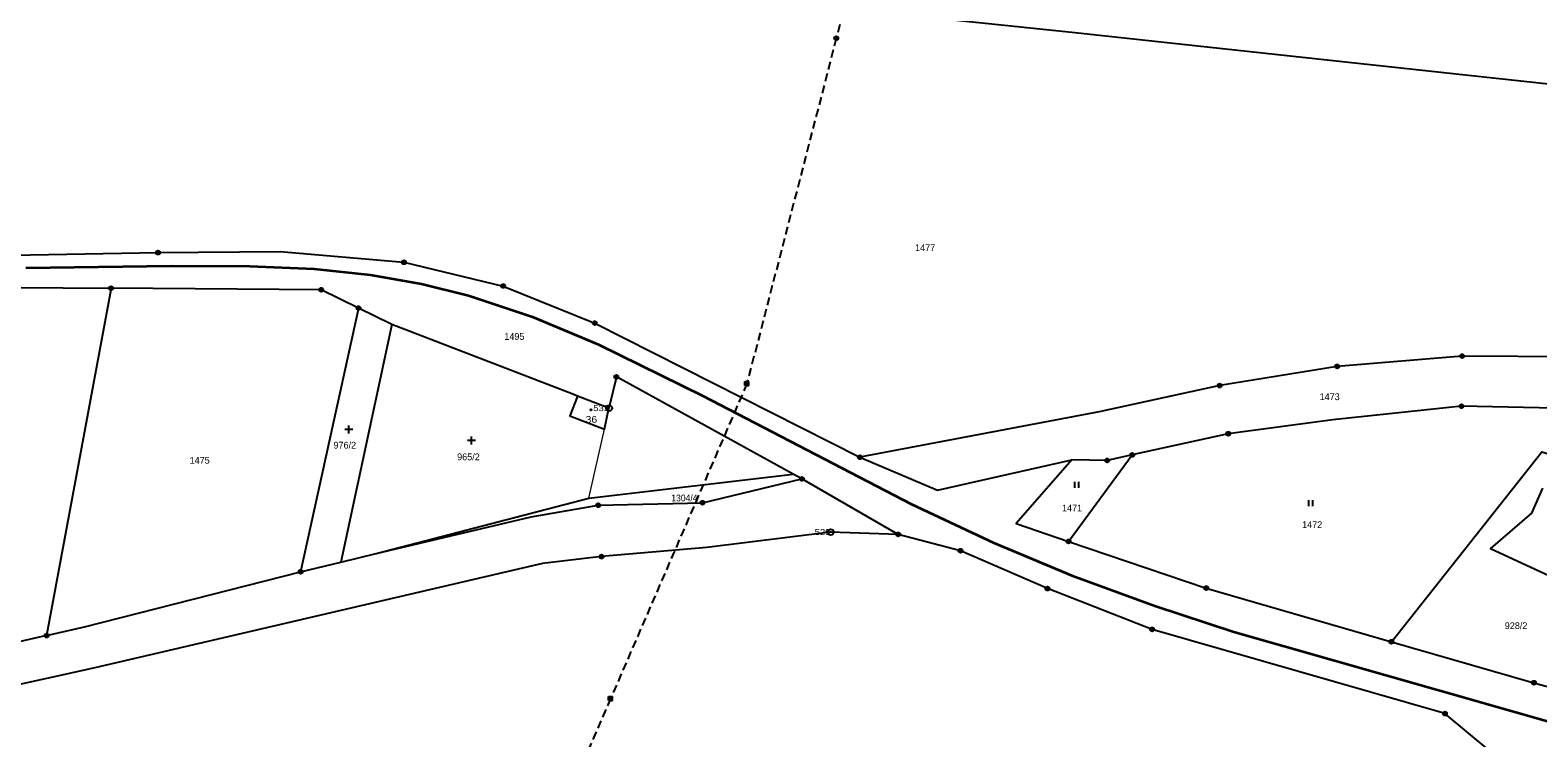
# Model space of a CAD drawing. Extents: x -872229 to -869198, y -1075981 to -1074329.
# Drawn here: x -871585.9 to -871207, y -1075387.5 to -1075209.5 of the extents above; entities that cross this region are included whole.
import ezdxf
from ezdxf.enums import TextEntityAlignment as Align

# ---------------------------------------------------------------- set-up
doc = ezdxf.new("R2010")
doc.units = 0
doc.header["$LTSCALE"] = 0.68
doc.linetypes.add('MEDIUM_DASHED', pattern=[4.5, 3, -1.5])
for name, color, linetype, lineweight in [('1', 7, 'Continuous', 25), ('3', 7, 'Continuous', 25), ('4', 7, 'Continuous', 13), ('5', 7, 'Continuous', 25), ('6', 7, 'Continuous', 25), ('8', 7, 'Continuous', 25)]:
    doc.layers.add(name, color=color, linetype=linetype, lineweight=lineweight)
doc.layers.add('2', color=7, linetype='Continuous')

msp = doc.modelspace()

# ---------------------------------------------------------------- linework, layer by layer
at = {"layer": '1'}
for p, q in [((-871391.97, -1075322.38), (-871394.16, -1075321.17)), ((-871367.76, -1075336.32), (-871391.97, -1075322.38)), ((-871517.94, -1075345.74), (-871507.87, -1075343.3))]:
    msp.add_line(p, q, dxfattribs=at)
for points in [[(-871152.53, -1075228.75), (-871324.15, -1075210.15), (-871498.95, -1075191.88), (-871564.6, -1075180.17), (-871590.36, -1075167.06), (-871608.79, -1075266.42)], [(-871673.37, -1075268.15), (-871670.8, -1075268.84), (-871646.86, -1075272.41), (-871613.89, -1075274.07), (-871565.58, -1075274.43)], [(-871608.79, -1075266.42), (-871553.79, -1075265.47), (-871523.09, -1075265.22), (-871491.97, -1075267.91), (-871467.05, -1075273.87), (-871444.01, -1075283.21), (-871377.38, -1075316.93)], [(-871503.38, -1075279.44), (-871512.76, -1075274.83), (-871565.58, -1075274.43), (-871581.77, -1075361.77)], [(-871495.01, -1075283.55), (-871503.38, -1075279.44), (-871517.94, -1075345.74)], [(-871495.01, -1075283.55), (-871507.87, -1075343.3), (-871498.97, -1075341.15)], [(-871448.37, -1075301.54), (-871449.54, -1075301.09), (-871495.01, -1075283.55)], [(-871197.94, -1075291.72), (-871226.01, -1075291.51), (-871257.41, -1075294.08), (-871286.96, -1075298.91), (-871317.28, -1075305.51), (-871377.38, -1075316.93)], [(-871394.16, -1075321.17), (-871438.58, -1075296.72), (-871440.45, -1075304.59)], [(-871198.89, -1075304.69), (-871226.19, -1075304.09), (-871258.51, -1075307.55), (-871284.79, -1075311.01), (-871308.94, -1075316.35)], [(-871243.8, -1075363.33), (-871206.01, -1075315.54), (-871202.96, -1075316.49), (-871198.89, -1075304.69)], [(-871377.38, -1075316.93), (-871357.91, -1075325.19), (-871324.12, -1075317.6)], [(-871324.12, -1075317.6), (-871338.12, -1075333.63), (-871324.93, -1075338.1), (-871308.94, -1075316.35)], [(-871308.94, -1075316.35), (-871315.25, -1075317.74), (-871324.12, -1075317.6)], [(-871498.97, -1075341.15), (-871445.51, -1075327.21), (-871394.16, -1075321.17)], [(-871498.97, -1075341.15), (-871459.98, -1075331.95), (-871443.14, -1075329), (-871416.95, -1075328.37), (-871391.97, -1075322.38)], [(-871205.8, -1075324.68), (-871208.57, -1075330.98), (-871218.91, -1075339.87), (-871180.67, -1075357.59)], [(-871367.76, -1075336.32), (-871384.74, -1075335.75), (-871415.81, -1075339.64), (-871442.3, -1075341.92), (-871457.12, -1075343.68), (-871569.63, -1075369.86), (-871593.96, -1075375.27), (-871613.49, -1075377.17), (-871630.54, -1075375.46), (-871654.44, -1075369.56), (-871683.36, -1075359.66)], [(-871212.24, -1075392.84), (-871218.94, -1075390.82), (-871230.33, -1075381.38), (-871303.93, -1075360.22), (-871330.24, -1075349.97), (-871352.11, -1075340.43), (-871367.76, -1075336.32)], [(-871581.77, -1075361.77), (-871595.26, -1075364.86), (-871610.89, -1075365.32), (-871627.46, -1075364.95), (-871651.19, -1075358.47), (-871705.48, -1075340.14)], [(-871324.93, -1075338.1), (-871290.33, -1075349.84), (-871243.8, -1075363.33)], [(-871581.77, -1075361.77), (-871572.27, -1075359.6), (-871517.94, -1075345.74)], [(-871243.8, -1075363.33), (-871207.98, -1075373.63), (-871201.2, -1075375.48), (-871200.62, -1075375.46)]]:
    msp.add_lwpolyline(points, dxfattribs=at)
msp.add_lwpolyline([(-871448.37, -1075301.54), (-871450.3, -1075306.53), (-871441.59, -1075309.84), (-871440.45, -1075304.59)], close=True, dxfattribs=at)
at = {"layer": '3'}
for p, q in [((-871504.829, -1075309.941), (-871506.831, -1075309.941)), ((-871505.83, -1075310.94), (-871505.83, -1075308.94)), ((-871473.959, -1075312.711), (-871475.961, -1075312.711)), ((-871474.96, -1075313.71), (-871474.96, -1075311.71)), ((-871323.381, -1075324.65), (-871323.381, -1075323.15)), ((-871322.38, -1075324.65), (-871322.38, -1075323.15)), ((-871264.561, -1075329.2), (-871264.561, -1075327.7)), ((-871263.56, -1075329.2), (-871263.56, -1075327.7))]:
    msp.add_line(p, q, dxfattribs=at)
at = {"layer": '4'}
msp.add_line((-871445.51, -1075327.21), (-871441.59, -1075309.84), dxfattribs=at)
at = {"layer": '5'}
msp.add_circle((-871444.9668, -1075305.0092), 0.175, dxfattribs=at)
at = {"layer": '6', "lineweight": 35}
for p, q in [((-871586.98, -1075269.26), (-871550.47, -1075268.77)), ((-871487.52, -1075273.3), (-871475.72, -1075276.29)), ((-871443.06, -1075288.59), (-871416.88, -1075301.49)), ((-871343.69, -1075338.47), (-871324.13, -1075346.64))]:
    msp.add_line(p, q, dxfattribs=at)
at = {"layer": '6', "linetype": 'MEDIUM_DASHED'}
msp.add_line((-871405.77, -1075298.4), (-871440.02, -1075377.58), dxfattribs=at)
at = {"layer": '6'}
for p, q in [((-871406.272, -1075297.899), (-871405.271, -1075297.899)), ((-871406.272, -1075298.899), (-871406.272, -1075297.899)), ((-871406.272, -1075298.099), (-871405.271, -1075298.099)), ((-871406.272, -1075298.299), (-871405.271, -1075298.299)), ((-871406.272, -1075298.499), (-871405.271, -1075298.499)), ((-871406.272, -1075298.699), (-871405.271, -1075298.699)), ((-871406.272, -1075298.899), (-871405.271, -1075298.899)), ((-871406.071, -1075298.899), (-871406.071, -1075297.899)), ((-871405.872, -1075298.899), (-871405.872, -1075297.899)), ((-871405.671, -1075298.899), (-871405.671, -1075297.899)), ((-871405.472, -1075298.899), (-871405.472, -1075297.899)), ((-871405.271, -1075298.899), (-871405.271, -1075297.899)), ((-871440.522, -1075377.079), (-871439.521, -1075377.079)), ((-871440.522, -1075378.079), (-871440.522, -1075377.079)), ((-871440.522, -1075377.279), (-871439.521, -1075377.279)), ((-871440.522, -1075377.479), (-871439.521, -1075377.479)), ((-871440.522, -1075377.679), (-871439.521, -1075377.679)), ((-871440.522, -1075377.879), (-871439.521, -1075377.879)), ((-871440.522, -1075378.079), (-871439.521, -1075378.079)), ((-871440.321, -1075378.079), (-871440.321, -1075377.079)), ((-871440.122, -1075378.079), (-871440.122, -1075377.079)), ((-871439.921, -1075378.079), (-871439.921, -1075377.079)), ((-871439.722, -1075378.079), (-871439.722, -1075377.079)), ((-871439.521, -1075378.079), (-871439.521, -1075377.079))]:
    msp.add_line(p, q, dxfattribs=at)
at = {"layer": '6', "linetype": 'MEDIUM_DASHED'}
for points in [[(-871372.59, -1075169.57), (-871383.31, -1075211.56), (-871405.77, -1075298.4)], [(-871440.02, -1075377.58), (-871476.16, -1075460.89), (-871517.14, -1075554.83)]]:
    msp.add_lwpolyline(points, dxfattribs=at)
at = {"layer": '6', "lineweight": 35}
for points in [[(-871550.47, -1075268.77), (-871530.68, -1075268.88), (-871514.5, -1075269.55)], [(-871514.5, -1075269.55), (-871500.36, -1075271.03), (-871487.52, -1075273.3)], [(-871475.72, -1075276.29), (-871459.68, -1075281.62), (-871443.06, -1075288.59)], [(-871416.88, -1075301.49), (-871364.43, -1075328.75), (-871343.69, -1075338.47)], [(-871324.13, -1075346.64), (-871303.26, -1075354.3), (-871283.38, -1075360.82)], [(-871283.38, -1075360.82), (-871232.19, -1075375.42), (-871192.83, -1075386.61)]]:
    msp.add_lwpolyline(points, dxfattribs=at)
at = {"layer": '6'}
for radius in [0.5, 0.4, 0.3, 0.2, 0.1]:
    msp.add_circle((-871383.3134, -1075211.5599), radius, dxfattribs=at)
at = {"layer": '8'}
for centre, radius in [((-871553.79, -1075265.4699), 0.5), ((-871553.79, -1075265.4699), 0.0303), ((-871491.97, -1075267.9099), 0.5), ((-871491.97, -1075267.9099), 0.0303), ((-871565.58, -1075274.4299), 0.5), ((-871565.58, -1075274.4299), 0.0303), ((-871512.76, -1075274.8299), 0.5), ((-871512.76, -1075274.8299), 0.0303), ((-871467.05, -1075273.8699), 0.5), ((-871467.05, -1075273.8699), 0.0303), ((-871503.38, -1075279.4399), 0.5), ((-871503.38, -1075279.4399), 0.0303), ((-871444.01, -1075283.2099), 0.5), ((-871444.01, -1075283.2099), 0.0303), ((-871226.01, -1075291.5099), 0.5), ((-871226.01, -1075291.5099), 0.0303), ((-871257.41, -1075294.0799), 0.5), ((-871257.41, -1075294.0799), 0.0303), ((-871438.58, -1075296.7199), 0.5), ((-871438.58, -1075296.7199), 0.0303), ((-871286.96, -1075298.9099), 0.5), ((-871286.96, -1075298.9099), 0.0303), ((-871440.39, -1075304.5798), 0.75), ((-871440.39, -1075304.5798), 0.03), ((-871226.19, -1075304.0899), 0.5), ((-871226.19, -1075304.0899), 0.0303), ((-871284.79, -1075311.0099), 0.5), ((-871284.79, -1075311.0099), 0.0303), ((-871377.38, -1075316.9299), 0.5), ((-871377.38, -1075316.9299), 0.0303), ((-871315.25, -1075317.7399), 0.5), ((-871315.25, -1075317.7399), 0.0303), ((-871308.94, -1075316.3499), 0.5), ((-871308.94, -1075316.3499), 0.0303), ((-871391.97, -1075322.3799), 0.5), ((-871391.97, -1075322.3799), 0.0303), ((-871443.14, -1075328.9999), 0.5), ((-871443.14, -1075328.9999), 0.0303), ((-871416.95, -1075328.3699), 0.5), ((-871416.95, -1075328.3699), 0.0303), ((-871384.74, -1075335.7498), 0.75), ((-871384.74, -1075335.7498), 0.03), ((-871367.76, -1075336.3199), 0.5), ((-871367.76, -1075336.3199), 0.0303), ((-871352.11, -1075340.4299), 0.5), ((-871352.11, -1075340.4299), 0.0303), ((-871324.93, -1075338.0999), 0.5), ((-871324.93, -1075338.0999), 0.0303), ((-871442.3, -1075341.9199), 0.5), ((-871442.3, -1075341.9199), 0.0303), ((-871517.94, -1075345.7399), 0.5), ((-871517.94, -1075345.7399), 0.0303), ((-871330.24, -1075349.9699), 0.5), ((-871330.24, -1075349.9699), 0.0303), ((-871290.33, -1075349.8399), 0.5), ((-871290.33, -1075349.8399), 0.0303), ((-871303.93, -1075360.2199), 0.5), ((-871581.77, -1075361.7699), 0.5), ((-871581.77, -1075361.7699), 0.0303), ((-871303.93, -1075360.2199), 0.0303), ((-871243.8, -1075363.3299), 0.5), ((-871243.8, -1075363.3299), 0.0303), ((-871207.98, -1075373.6299), 0.5), ((-871207.98, -1075373.6299), 0.0303), ((-871230.33, -1075381.3799), 0.5), ((-871230.33, -1075381.3799), 0.0303)]:
    msp.add_circle(centre, radius, dxfattribs=at)

# ---------------------------------------------------------------- texts
at = {"layer": '2'}
for s, p in [('1477', (-871363.52, -1075265.11)), ('1495', (-871466.75, -1075287.41)), ('1473', (-871261.85, -1075302.57)), ('976/2', (-871509.68, -1075314.75)), ('1475', (-871545.84, -1075318.56)), ('965/2', (-871478.6, -1075317.68)), ('1471', (-871326.59, -1075330.57)), ('1472', (-871266.24, -1075334.73)), ('928/2', (-871215.31, -1075360.14))]:
    msp.add_text(s, height=1.7, dxfattribs=at).set_placement(p)
for s, width, p in [('36', 1.15, (-871446.32, -1075308.28)), ('1304/4', 0.95, (-871424.79, -1075328.02))]:
    msp.add_text(s, height=1.7, dxfattribs=dict(at, width=width)).set_placement(p)
at = {"layer": '8', "width": 1.2}
for s, p in [('533', (-871440.39, -1075305.33)), ('529', (-871384.74, -1075336.5))]:
    msp.add_text(s, height=1.5, dxfattribs=at).set_placement(p, align=Align.RIGHT)

doc.saveas('drawing.dxf')
